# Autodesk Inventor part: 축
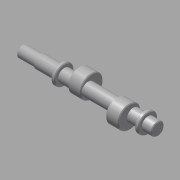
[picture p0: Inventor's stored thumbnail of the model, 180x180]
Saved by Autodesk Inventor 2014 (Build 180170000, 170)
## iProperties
Created: 2013-02
Part Number: 축
Document SubType Name: Modeling
Designer: 한국산업디자인학원[gmhk.co.kr]
Density: 7.86 g/cm^3
Material: 강철, 연강
Appearance: 강철
Mass: 458.535 g
Surface Area: 143.366 cm^2
Volume: 58.3377 cm^3
Author: 한국산업디자인학원[gmhk.co.kr]
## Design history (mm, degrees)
sketch "스케치2"
  geometry: L1 (-58, 84.5)-(-58, 15.5) reference; L2 (58, 15.5)-(58, 84.5) reference; L3 (-85, 25.774)-(-85, 74.226) reference; L4 (70, 84.185)-(70, 15.815) reference; L5 (71, 50)-(-109, 50); L6 (69.4, 58.5)-(58.6, 58.5) reference; L7 (71, 50)-(71, 58.5); L8 (71, 58.5)-(58, 58.5); L9 (58, 58.5)-(58, 63); L10 (58, 63)-(53, 63); L11 (53, 63)-(53, 58.5); L12 (53, 58.5)-(-53, 58.5); L13 (-53, 58.5)-(-53, 63); L14 (-53, 63)-(-58, 63); L15 (-58, 63)-(-58, 58.5); L16 (-58, 58.5)-(-85, 58.5); L17 (-85, 58.5)-(-85, 57.5); L18 (-85, 57.5)-(-109, 57.5); L19 (-109, 57.5)-(-109, 50); L20 (-30, 102.5)-(-30, 50); L21 (30, 102.5)-(30, 50); L22 (-50, 102.5)-(-10, 102.5) reference; L23 (10, 102.5)-(50, 102.5) reference; 2 further points
  constraints: 34 end point, 10 perpendicular, 9 point on line, 5 collinear, 3 midpoint, 3 parallel, 1 horizontal, 2 other
  dimensions: "d0" = 1 distance between parallel lines of L7 L4; "d1" = 26 diameter of L10 L5; "d2" = 5 distance of L9.end L10.end; "d3" = 5 distance of L13.end L14.end (= d2); "d4" = 180 distance of L5.start L5.end; "d5" = 15 diameter of L18 L5
  node "참조1"
  node "참조2"
  node "참조3"
  node "참조4"
  node "참조7"
  node "참조8"
revolve "회전1" stored, may be unused: angle "d6" = 90 deg
node "작업 평면1"
sketch "스케치3"
  geometry: C1 r 8.5 at (52.5, 0) reference; C2 r 15 at (47.5, 0); 1 further point
  constraints: 1 centre point, 1 horizontal alignment
  dimensions: "d8" = 5 distance of C1.centre C2.centre; "d9" = 30 diameter of C2
extrude "돌출1" join sketch "스케치3" stored distance "d10" = 17; taper "d11" = 0 deg
node "작업 평면2"
sketch "스케치4"
  geometry: C1 r 8.5 at (52.5, 0) reference; C2 r 15 at (57.5, 0); 1 further point
  constraints: 1 centre point, 1 horizontal alignment
  dimensions: "d13" = 5 distance of C2.centre C1.centre; "d14" = 30 diameter of C2
extrude "돌출2" join sketch "스케치4" stored distance "d15" = 17; taper "d16" = 0 deg
chamfer "모따기1" distance "d17" = 1; stored, may be unused: second distance "d18" = 2, angle "d19" = 45 deg
node "작업 평면3"
sketch "스케치5"
  geometry: L1 (12, 6.5)-(12, -6.5) reference; L2 (12, 2.5)-(-5.5, 2.5); L3 (-5.5, -2.5)-(12, -2.5); A1 r 2.5 centre (-5.5, 0) between (-5.5, 2.5) and (-5.5, -2.5); 2 further points
  constraints: 4 end point, 2 point on circle, 2 point on line, 2 tangent, 1 centre point, 1 horizontal alignment, 1 midpoint, 1 parallel, 1 perpendicular
  dimensions: "d20" = 5 distance between parallel lines of L3 L2; "d21" = 20 dimension on A1 L1
extrude "돌출3" cut sketch "스케치5" distance "d22" = 3; taper "d23" = 0 deg
chamfer "모따기2" distance "d24" = 1; stored, may be unused: second distance "d25" = 2, angle "d26" = 45 deg
node "솔리드1"
node "투영된 루프1"
node "투영된 루프2"
other parameters: "d7" = 0, "d12" = 0
